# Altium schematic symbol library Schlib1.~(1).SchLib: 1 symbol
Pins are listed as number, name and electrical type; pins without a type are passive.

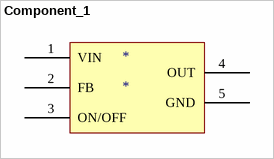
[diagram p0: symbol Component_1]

## Component_1
designator *
footprint TO263-5A (263，5脚晶体管)
pins: 1 VIN, 2 FB, 3 ON/OFF, 4 OUT, 5 GND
